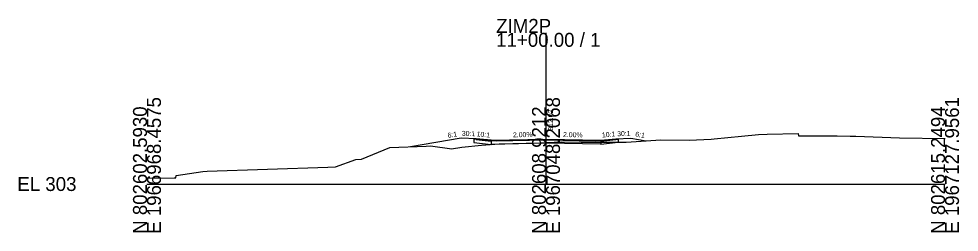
# Model space of a CAD drawing. Extents: x 1950845 to 1951408, y 736831 to 740365.
# Drawn here: x 1950844.5 to 1951033.1, y 737831.5 to 737874.4 of the extents above; entities that cross this region are included whole.
import ezdxf

# ---------------------------------------------------------------- set-up
doc = ezdxf.new("R2010")
doc.units = 0
for name, color, linetype in [('RD_GPK_XS_Cell', 7, 'Continuous'), ('RD_XS_Base', 7, 'Continuous'), ('RD_XS_EarthShd', 7, 'Continuous'), ('RD_XS_ExGround', 7, 'Continuous'), ('RD_XS_Pave', 7, 'Continuous'), ('RD_XS_PaveOvlay', 7, 'Continuous'), ('RD_XS_TieSlope', 7, 'Continuous'), ('RD_XS_TX_Elev_PR', 7, 'Continuous'), ('RD_XS_TX_Slope', 7, 'Continuous')]:
    doc.layers.add(name, color=color, linetype=linetype)

msp = doc.modelspace()

# ---------------------------------------------------------------- linework, layer by layer
at = {"layer": 'RD_GPK_XS_Cell'}
for p, q in [((1950950.22, 737841.19), (1950950.22, 737871.58)), ((1950870.22, 737841.19), (1950950.22, 737841.19)), ((1950950.22, 737841.19), (1951030.22, 737841.19))]:
    msp.add_line(p, q, dxfattribs=at)
at = {"layer": 'RD_XS_Base'}
for points in [[(1950939.22, 737849.83), (1950936.22, 737850.13), (1950935.72, 737850.18)], [(1950935.72, 737850.18), (1950935.72, 737849.52)], [(1950935.72, 737849.52), (1950939.22, 737849.17)], [(1950939.22, 737849.83), (1950939.22, 737849.17)], [(1950961.22, 737849.18), (1950950.22, 737849.39), (1950939.22, 737849.17)], [(1950940.22, 737849.85), (1950950.22, 737850.05), (1950960.22, 737849.85)], [(1950961.22, 737849.83), (1950964.22, 737850.13), (1950964.72, 737850.18)], [(1950961.22, 737849.83), (1950961.22, 737849.17)], [(1950964.72, 737849.52), (1950961.22, 737849.17)], [(1950964.72, 737850.18), (1950964.72, 737849.52)]]:
    msp.add_lwpolyline(points, dxfattribs=at)
at = {"layer": 'RD_XS_EarthShd'}
for points in [[(1950936.22, 737850.29), (1950933.22, 737850.39)], [(1950964.22, 737850.29), (1950967.22, 737850.39)]]:
    msp.add_lwpolyline(points, dxfattribs=at)
at = {"layer": 'RD_XS_ExGround'}
msp.add_lwpolyline([(1950870.22, 737842.37), (1950875.68, 737842.45), (1950875.99, 737842.45), (1950876.1, 737842.9), (1950881.44, 737843.68), (1950882.26, 737843.77), (1950906.49, 737844.58), (1950907.99, 737844.66), (1950912.11, 737846.13), (1950913.25, 737846.2), (1950918.93, 737848.52), (1950926.19, 737848.83), (1950927.12, 737848.84), (1950927.53, 737848.83), (1950930.9, 737848.31), (1950931.29, 737848.28), (1950933.36, 737848.61), (1950937.27, 737849.02), (1950940.84, 737849.29), (1950948.97, 737849.5), (1950950.22, 737849.55), (1950953.42, 737849.67), (1950957.26, 737849.61), (1950966.28, 737849.6), (1950973.26, 737850.07), (1950978.92, 737850), (1950983.3, 737850.24), (1950983.92, 737850.31), (1950989.4, 737850.84), (1950992.79, 737851.16), (1950994.53, 737851.21), (1951000.77, 737851.32), (1951000.87, 737850.87), (1951001.82, 737850.87), (1951008.6, 737850.89), (1951011.19, 737850.84), (1951012.35, 737850.84), (1951021.12, 737850.46), (1951030.22, 737850.35)], dxfattribs=at)
at = {"layer": 'RD_XS_Pave'}
for points in [[(1950939.22, 737849.99), (1950936.22, 737850.29)], [(1950936.22, 737850.29), (1950936.22, 737850.13)], [(1950936.22, 737850.13), (1950939.22, 737849.83)], [(1950939.22, 737849.83), (1950939.22, 737849.99)], [(1950961.22, 737849.99), (1950964.22, 737850.29)], [(1950964.22, 737850.13), (1950961.22, 737849.83)], [(1950961.22, 737849.83), (1950961.22, 737849.99)], [(1950964.22, 737850.29), (1950964.22, 737850.13)]]:
    msp.add_lwpolyline(points, dxfattribs=at)
at = {"layer": 'RD_XS_PaveOvlay'}
for points in [[(1950939.22, 737849.99), (1950950.22, 737850.21), (1950961.22, 737849.99)], [(1950961.22, 737849.83), (1950950.22, 737850.05), (1950939.22, 737849.83)], [(1950939.22, 737849.99), (1950939.22, 737849.83)], [(1950961.22, 737849.99), (1950961.22, 737849.83)]]:
    msp.add_lwpolyline(points, dxfattribs=at)
at = {"layer": 'RD_XS_TieSlope'}
for points in [[(1950933.22, 737850.39), (1950923.06, 737848.7)], [(1950967.22, 737850.39), (1950970.31, 737849.87)]]:
    msp.add_lwpolyline(points, dxfattribs=at)

# ---------------------------------------------------------------- texts
at = {"layer": 'RD_GPK_XS_Cell'}
for s, p in [('ZIM2P', (1950940.22, 737871.58)), ('11+00.00 / 1', (1950940.22, 737868.78)), ('EL 303', (1950844.22, 737839.79))]:
    msp.add_text(s, height=2.8, dxfattribs=at).set_placement(p)
for s, p in [('E 1966968.4575', (1950873.02, 737831.19)), ('E 1967048.2068', (1950953.02, 737831.19)), ('E 1967127.9561', (1951033.02, 737831.19)), ('N 802602.5930', (1950870.22, 737831.19)), ('N 802608.9212', (1950950.22, 737831.19)), ('N 802615.2494', (1951030.22, 737831.19))]:
    msp.add_text(s, height=2.8, rotation=90, dxfattribs=at).set_placement(p)
at = {"layer": 'RD_XS_TX_Elev_PR'}
msp.add_text('312.02', height=1, rotation=90, dxfattribs=at).set_placement((1950951.63, 737851.92))
at = {"layer": 'RD_XS_TX_Slope'}
for s, rotation, p in [('6:1', 9.4642, (1950930.57, 737850.46)), ('30:1', 358.0908, (1950933.33, 737850.89)), ('10:1', 354.2894, (1950936.28, 737850.79)), ('2.00%', 1.1458, (1950943.61, 737850.58)), ('2.00%', 358.8542, (1950953.63, 737850.64)), ('10:1', 5.7106, (1950961.48, 737850.52)), ('30:1', 1.9092, (1950964.5, 737850.8)), ('6:1', 350.5358, (1950968.06, 737850.76))]:
    msp.add_text(s, height=1, rotation=rotation, dxfattribs=at).set_placement(p)

doc.saveas('drawing.dxf')
